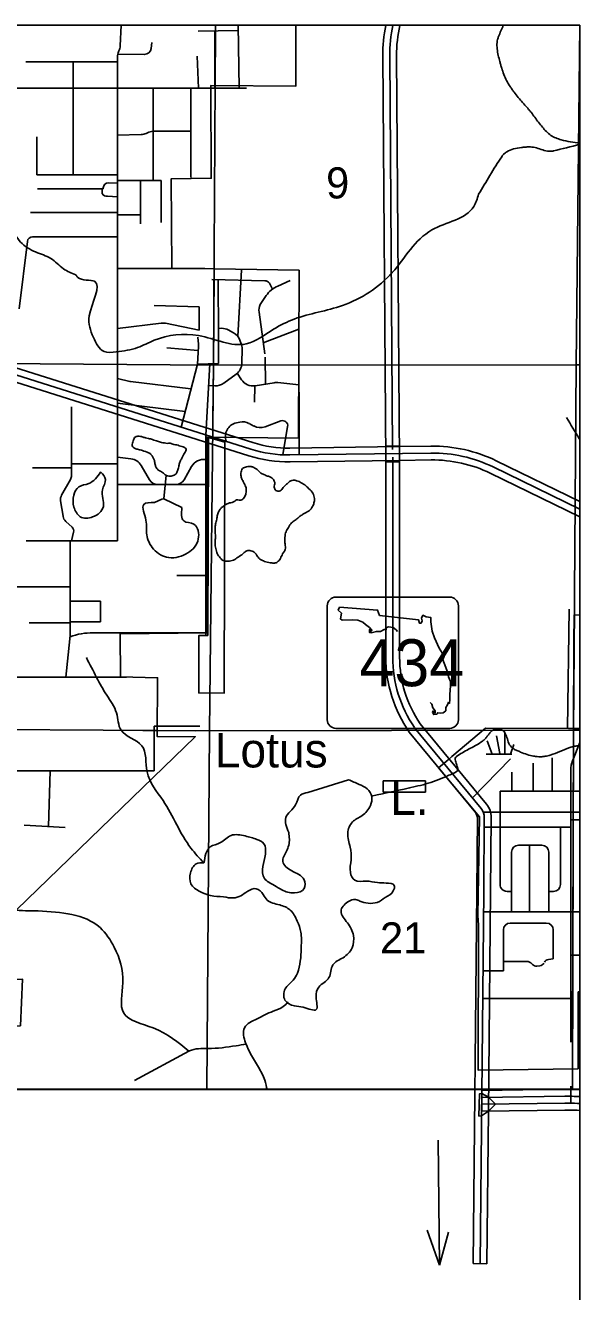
# Model space of a CAD drawing. Extents: x 2157516 to 2331756, y 2153820 to 2265756.
# Drawn here: x 2249249 to 2265958, y 2184545 to 2222724 of the extents above; entities that cross this region are included whole.
import ezdxf

# ---------------------------------------------------------------- set-up
doc = ezdxf.new("R2010")
doc.units = 0
doc.layers.add('Default', color=7, linetype='Continuous')
doc.layers.add('MapOutline_dp', color=7, linetype='Continuous')

msp = doc.modelspace()

# ---------------------------------------------------------------- linework, layer by layer
at = {"layer": 'Default'}
for p, q in [((2252133, 2222724), (2252107, 2222104)), ((2254463, 2222547), (2255663, 2222570)), ((2254980, 2222724), (2254920, 2212483)), ((2254958, 2220833), (2254958, 2222556)), ((2254980, 2222724), (2254969, 2220790)), ((2255697, 2220833), (2255660, 2222724)), ((2265958, 2222724), (2265856, 2212486)), ((2253065, 2222206), (2253043, 2222030)), ((2249263, 2221619), (2252030, 2221619)), ((2250686, 2220833), (2250686, 2221619)), ((2252030, 2221813), (2252030, 2220833)), ((2252836, 2221847), (2252033, 2221852)), ((2252072, 2221953), (2252047, 2221897)), ((2254468, 2220833), (2254429, 2221795)), ((2260023, 2221802), (2260113, 2209601)), ((2260232, 2221803), (2260320, 2209934)), ((2260440, 2221805), (2260530, 2209607)), ((2247650, 2220833), (2255920, 2220833)), ((2250686, 2218217), (2250686, 2220833)), ((2252030, 2211213), (2252030, 2220833)), ((2253099, 2218042), (2253099, 2220833)), ((2254238, 2218135), (2254238, 2220833)), ((2249596, 2219357), (2249596, 2218217)), ((2252030, 2219409), (2252740, 2219429)), ((2252890, 2219462), (2252975, 2219498)), ((2253137, 2219531), (2254238, 2219531)), ((2249596, 2218217), (2252030, 2218217)), ((2249613, 2217792), (2251597, 2217792)), ((2251565, 2217792), (2251564, 2217648)), ((2251597, 2217792), (2251599, 2217827)), ((2251758, 2217975), (2252030, 2217970)), ((2252030, 2218042), (2253340, 2218042)), ((2252720, 2216736), (2252720, 2218042)), ((2253340, 2218042), (2253340, 2216782)), ((2251730, 2217572), (2252030, 2217555)), ((2249405, 2217085), (2252030, 2217085)), ((2252030, 2217010), (2252720, 2217010)), ((2252030, 2216345), (2249466, 2216345)), ((2249311, 2216208), (2249064, 2214181)), ((2252030, 2215388), (2254655, 2215388)), ((2255659, 2213338), (2255761, 2215351)), ((2254866, 2215064), (2256473, 2215025)), ((2255066, 2215059), (2255071, 2213397)), ((2256605, 2214946), (2256703, 2214773)), ((2257229, 2215030), (2256857, 2214863)), ((2256511, 2214574), (2256327, 2214305)), ((2254484, 2214236), (2253128, 2214277)), ((2254484, 2213537), (2254484, 2214236)), ((2256294, 2214078), (2256466, 2212819)), ((2252030, 2213579), (2253339, 2213746)), ((2253475, 2213742), (2254484, 2213537)), ((2255071, 2213588), (2255166, 2213591)), ((2254446, 2213321), (2254468, 2213116)), ((2255071, 2213397), (2255074, 2212530)), ((2255366, 2213540), (2255526, 2213453)), ((2255715, 2213236), (2255758, 2213125)), ((2256420, 2213154), (2257491, 2213561)), ((2257491, 2213561), (2257500, 2209774)), ((2254461, 2212924), (2253519, 2212996)), ((2254469, 2213045), (2254434, 2212506)), ((2255785, 2212969), (2255776, 2212537)), ((2254920, 2212483), (2243791, 2212557)), ((2247922, 2212509), (2256048, 2209944)), ((2256048, 2209944), (2247922, 2212509)), ((2247984, 2212708), (2256111, 2210143)), ((2254434, 2212506), (2253944, 2210608)), ((2255074, 2212530), (2254434, 2212506)), ((2254692, 2210372), (2254808, 2212520)), ((2254920, 2212483), (2254804, 2201455)), ((2265856, 2212486), (2254920, 2212483)), ((2256474, 2212717), (2256484, 2211907)), ((2265856, 2212486), (2265772, 2201473)), ((2265958, 2212485), (2265856, 2212486)), ((2255985, 2209746), (2247859, 2212311)), ((2252030, 2212081), (2252403, 2211989)), ((2255604, 2212208), (2255229, 2211936)), ((2255635, 2212232), (2255765, 2212038)), ((2252415, 2211987), (2252403, 2211989)), ((2252415, 2211987), (2254242, 2211762)), ((2254958, 2211857), (2254773, 2211869)), ((2256164, 2211857), (2256156, 2211366)), ((2256176, 2211859), (2256750, 2211949)), ((2256750, 2211949), (2256750, 2211949)), ((2256856, 2211953), (2257495, 2211889)), ((2252030, 2211328), (2254066, 2211082)), ((2250640, 2209156), (2250640, 2211217)), ((2252030, 2211213), (2252030, 2207181)), ((2255612, 2210739), (2255711, 2210760)), ((2255991, 2210722), (2256139, 2210644)), ((2256476, 2210622), (2256948, 2210796)), ((2257156, 2210624), (2257013, 2209774)), ((2254692, 2204329), (2254692, 2210372)), ((2257223, 2209979), (2260527, 2210023)), ((2257226, 2209771), (2261475, 2209827)), ((2261475, 2209827), (2257226, 2209771)), ((2260527, 2210023), (2261473, 2210036)), ((2249463, 2209386), (2250640, 2209386)), ((2250640, 2209506), (2252030, 2209506)), ((2252030, 2209706), (2252433, 2209657)), ((2252742, 2209454), (2252996, 2209018)), ((2254260, 2209424), (2254032, 2209021)), ((2260528, 2209607), (2257229, 2209562)), ((2260113, 2209601), (2260113, 2203674)), ((2260322, 2209701), (2260322, 2203674)), ((2261478, 2209619), (2260528, 2209607)), ((2260530, 2209607), (2260530, 2203674)), ((2263353, 2209408), (2265958, 2208140)), ((2265958, 2208140), (2263353, 2209408)), ((2263444, 2209595), (2265958, 2208372)), ((2250343, 2208559), (2250607, 2209028)), ((2251526, 2209253), (2251518, 2209253)), ((2253419, 2208446), (2253496, 2209157)), ((2265958, 2207909), (2263262, 2209221)), ((2252030, 2208878), (2254692, 2208878)), ((2250386, 2207921), (2250312, 2208391)), ((2255398, 2208326), (2255401, 2208328)), ((2250656, 2207596), (2250467, 2207769)), ((2252030, 2207181), (2249272, 2207181)), ((2250599, 2204396), (2250599, 2207181)), ((2250640, 2207181), (2250702, 2207445)), ((2250640, 2207181), (2250640, 2207181)), ((2253814, 2206141), (2254692, 2206141)), ((2242378, 2205792), (2250599, 2205792)), ((2250599, 2205368), (2251514, 2205368)), ((2251514, 2205368), (2251514, 2204744)), ((2258348, 2205224), (2258348, 2201789)), ((2262043, 2205484), (2258608, 2205484)), ((2262303, 2201789), (2262303, 2205224)), ((2265640, 2205124), (2265589, 2201528)), ((2249367, 2204710), (2250599, 2204710)), ((2251514, 2204744), (2250599, 2204744)), ((2254747, 2204411), (2251296, 2204411)), ((2250473, 2203067), (2250590, 2204229)), ((2243735, 2203067), (2252299, 2203067)), ((2254804, 2201455), (2243775, 2201524)), ((2252794, 2201468), (2254392, 2201458)), ((2253136, 2200251), (2253136, 2201591)), ((2253136, 2201591), (2254510, 2201591)), ((2254804, 2201455), (2254715, 2190662)), ((2265772, 2201473), (2254804, 2201455)), ((2258608, 2201529), (2262043, 2201529)), ((2260822, 2201417), (2262829, 2198979)), ((2260982, 2201549), (2262990, 2199112)), ((2263150, 2199244), (2261154, 2201667)), ((2263701, 2201426), (2263701, 2200747)), ((2265620, 2201528), (2265958, 2201528)), ((2265772, 2201473), (2265740, 2190663)), ((2265958, 2201472), (2265772, 2201473)), ((2263173, 2201149), (2263324, 2200747)), ((2263450, 2201300), (2263550, 2200772)), ((2263975, 2201041), (2263877, 2200747)), ((2265958, 2201103), (2265747, 2200568)), ((2262725, 2199433), (2263872, 2200609)), ((2263137, 2200747), (2263913, 2200747)), ((2265128, 2199632), (2265128, 2200638)), ((2243735, 2200251), (2253136, 2200251)), ((2250000, 2200251), (2249951, 2198565)), ((2264554, 2199632), (2264554, 2200484)), ((2265689, 2200263), (2265689, 2193050)), ((2257764, 2199592), (2258988, 2199981)), ((2263913, 2199632), (2263913, 2200203)), ((2265958, 2199632), (2263560, 2199632)), ((2263560, 2199632), (2263560, 2196822)), ((2262829, 2198979), (2262876, 2198845)), ((2262876, 2198845), (2262858, 2196614)), ((2265958, 2198999), (2263056, 2198999)), ((2263084, 2198843), (2263066, 2196612)), ((2263274, 2196611), (2263293, 2198842)), ((2265689, 2198766), (2265958, 2198766)), ((2249218, 2198609), (2250448, 2198535)), ((2263082, 2198546), (2265689, 2198546)), ((2265382, 2196820), (2265382, 2198546)), ((2264820, 2198005), (2264113, 2198005)), ((2264450, 2195996), (2264450, 2198005)), ((2263905, 2197797), (2263905, 2195996)), ((2265028, 2195996), (2265028, 2197797)), ((2262858, 2196614), (2262746, 2185391)), ((2263066, 2196612), (2262954, 2185389)), ((2263208, 2189990), (2263274, 2196611)), ((2263768, 2196614), (2263905, 2196614)), ((2265028, 2196612), (2265173, 2196612)), ((2263060, 2195996), (2265958, 2195996)), ((2264953, 2195659), (2263868, 2195659)), ((2263660, 2195451), (2263660, 2194216)), ((2265161, 2194582), (2265161, 2195451)), ((2263668, 2194503), (2264360, 2194503)), ((2265016, 2194564), (2265161, 2194582)), ((2265689, 2194690), (2265958, 2194690)), ((2263660, 2194216), (2263042, 2194216)), ((2264519, 2194429), (2264534, 2194411)), ((2264671, 2194357), (2264760, 2194367)), ((2263034, 2193384), (2265689, 2193384)), ((2265909, 2193586), (2265958, 2193585)), ((2265689, 2193050), (2265691, 2192068)), ((2254182, 2191797), (2252538, 2190909)), ((2265692, 2190740), (2265693, 2190229)), ((2263000, 2189987), (2263004, 2190403)), ((2263001, 2190611), (2265504, 2190646)), ((2263004, 2190403), (2265507, 2190438)), ((2263163, 2185387), (2263208, 2189990)), ((2261729, 2185341), (2261696, 2189112)), ((2261729, 2185341), (2261366, 2186396)), ((2261729, 2185341), (2262004, 2186341)), ((2262746, 2185391), (2263163, 2185387)), ((2262746, 2185391), (2263163, 2185387))]:
    msp.add_line(p, q, dxfattribs=at)
for points in [[(2265958, 2190664), (2245319, 2190652), (2245307, 2191654), (2245319, 2192549), (2249099, 2192561), (2249167, 2193966), (2246762, 2193921), (2254372, 2201275), (2253227, 2201282), (2253233, 2203055), (2252119, 2203079), (2252103, 2204383), (2254726, 2204410), (2254718, 2210303), (2257483, 2210276), (2257499, 2215340), (2253665, 2215400), (2253649, 2218097), (2254852, 2218113), (2254836, 2220906), (2257403, 2220890), (2257403, 2222724)], [(2254936, 2215232), (2254920, 2212483), (2254903, 2210838)], [(2253968, 2208184), (2253419, 2208446), (2253366, 2208435), (2253145, 2208341)], [(2260470, 2204445), (2260429, 2204498), (2260340, 2204574), (2260196, 2204594), (2260134, 2204567), (2260127, 2204505), (2260066, 2204512), (2259956, 2204450), (2259832, 2204450), (2259674, 2204409), (2259619, 2204423), (2259626, 2204512), (2259661, 2204450), (2259695, 2204484), (2259619, 2204574), (2259503, 2204663), (2259427, 2204725), (2259276, 2204793), (2259118, 2204800), (2258796, 2204793), (2258748, 2204828), (2258775, 2205006), (2258679, 2205096), (2258714, 2205178)], [(2258714, 2205178), (2259866, 2205096), (2259928, 2204931), (2261102, 2204800), (2261129, 2204704), (2261177, 2204704), (2261212, 2204773), (2261191, 2204855), (2261232, 2204938), (2261335, 2204890), (2261472, 2204869), (2261472, 2204739), (2261514, 2204457), (2261582, 2204258), (2261726, 2203949), (2261822, 2203784), (2261877, 2203709), (2261836, 2203592), (2261891, 2203448), (2261960, 2203248), (2262008, 2203084), (2262063, 2202939), (2262063, 2202809), (2262049, 2202548), (2262042, 2202397), (2262035, 2202280), (2262008, 2202315), (2261973, 2202239), (2261925, 2202157), (2261925, 2202061), (2261843, 2201999), (2261754, 2201985), (2261678, 2201999), (2261651, 2201958), (2261562, 2201944), (2261520, 2202019), (2261541, 2202054), (2261568, 2202006), (2261603, 2201992), (2261603, 2202054), (2261527, 2202143), (2261500, 2202253), (2261453, 2202304)], [(2265958, 2204945), (2265793, 2204949), (2265787, 2204131), (2265772, 2201524), (2263123, 2201539), (2262108, 2200675), (2261990, 2200578), (2261698, 2200334), (2262937, 2198857), (2262889, 2195888), (2262913, 2195592), (2262900, 2191220), (2265908, 2191265), (2265909, 2193586)], [(2265800, 2205138), (2265772, 2201473), (2265744, 2192040)], [(2233007, 2190644), (2265958, 2190644)], [(2263004, 2190403), (2265507, 2190438), (2265608, 2190439), (2265707, 2190437), (2265807, 2190434), (2265907, 2190430), (2265958, 2190426)], [(2265958, 2190009), (2265884, 2190014), (2265791, 2190018), (2265697, 2190021), (2265606, 2190022), (2265512, 2190022), (2263000, 2189987)], [(2263002, 2190195), (2265510, 2190230), (2265607, 2190231), (2265702, 2190229), (2265799, 2190226), (2265896, 2190222), (2265958, 2190218)]]:
    msp.add_lwpolyline(points, dxfattribs=at)
for points in [[(2254773, 2210302), (2254746, 2204329), (2254480, 2204330), (2254477, 2202595), (2255246, 2202593), (2255260, 2210157)], [(2260116, 2210040), (2260523, 2210040), (2260523, 2209560), (2260116, 2209560)], [(2260039, 2199944), (2261308, 2199944), (2261308, 2199609), (2260039, 2199609)], [(2263005, 2190520), (2263213, 2190406), (2263419, 2190201), (2263208, 2189990), (2262999, 2189845), (2262919, 2189839), (2262943, 2190514)]]:
    msp.add_lwpolyline(points, close=True, dxfattribs=at)
for centre, radius, start, end in [((2264395, 2221834), 4372, 168.2633, 180.4261), ((2264395, 2221834), 4164, 167.6675, 180.4261), ((2264395, 2221834), 3956, 167.0073, 180.4261), ((2251691, 2222122), 416, 336.1246, 357.6139), ((2252837, 2222055), 208, 269.6876, 352.875), ((2252238, 2221813), 208, 156.1244, 179.9999), ((2252728, 2219846), 416, 271.6516, 292.9324), ((2253137, 2219115), 416, 90, 112.9325), ((2251755, 2217819), 156, 88.939, 177.3018), ((2251700, 2217725), 156, 209.3577, 281.3099), ((2249466, 2216189), 156, 90, 173.0636), ((2256469, 2214869), 156, 29.5387, 88.614), ((2257198, 2214104), 833, 114.2012, 145.5977), ((2256707, 2214134), 416, 155.8714, 187.7869), ((2253392, 2213333), 416, 78.5412, 97.3006), ((2255166, 2213175), 416, 61.3268, 90), ((2255326, 2213087), 416, 20.8533, 61.3271), ((2254054, 2213072), 416, 356.2276, 6.054), ((2255368, 2212977), 416, 358.8765, 20.8543), ((2255360, 2212545), 416, 305.9523, 358.8767), ((2254984, 2212273), 416, 266.4237, 305.9523), ((2256111, 2212270), 416, 213.8509, 279.0017), ((2256815, 2211538), 416, 84.3594, 99.0016), ((2255698, 2210332), 416, 101.9293, 201.8651), ((2255797, 2210353), 416, 62.354, 101.9291), ((2256332, 2211013), 416, 242.3538, 290.2727), ((2257002, 2210650), 156, 350.4889, 110.2726), ((2257176, 2213518), 3539, 252.4813, 270.7668), ((2257176, 2213518), 3747, 252.4813, 270.7668), ((2257176, 2213518), 3747, 252.4813, 270.7668), ((2261531, 2205664), 4372, 64.0482, 90.7668), ((2261531, 2205664), 4164, 64.0482, 90.7668), ((2261531, 2205664), 4164, 64.0482, 90.7668), ((2252382, 2209244), 416, 30.2879, 83.0463), ((2254622, 2209219), 416, 80.4042, 150.4948), ((2257176, 2213518), 3956, 252.4813, 270.7668), ((2261531, 2205664), 3956, 64.0482, 90.7668), ((2250380, 2209156), 260, 330.6039, 359.9999), ((2253239, 2209159), 281, 210.2878, 269.9999), ((2253787, 2209159), 281, 270, 330.4949), ((2250569, 2208431), 260, 150.6039, 188.9453), ((2250643, 2207961), 260, 188.9451, 227.3858), ((2250550, 2207481), 156, 346.7592, 47.3859), ((2258608, 2205224), 260, 90, 180), ((2262043, 2205224), 260, 0, 90), ((2251296, 2202329), 2082, 90, 109.6672), ((2248933, 2204396), 1665, 354.2237, 359.9998), ((2264097, 2203684), 3984, 180.1462, 214.6899), ((2264069, 2203674), 3747, 179.9998, 214.5435), ((2264069, 2203674), 3539, 179.9998, 214.5435), ((2258608, 2201789), 260, 180, 270), ((2262043, 2201789), 260, 270, 360), ((2266522, 2200263), 833, 158.5232, 179.9998), ((2262668, 2198847), 416, 359.5254, 39.4733), ((2262668, 2198847), 625, 359.5254, 39.4733), ((2264113, 2197797), 208, 90, 179.9999), ((2264820, 2197797), 208, 359.9998, 89.9998), ((2263768, 2196822), 208, 179.9998, 269.9998), ((2265173, 2196820), 208, 270, 359.9999), ((2263868, 2195451), 208, 90, 179.9999), ((2264953, 2195451), 208, 359.9998, 89.9998), ((2264360, 2194295), 208, 40.0302, 89.9999), ((2265035, 2194409), 156, 97.125, 153.4349), ((2264653, 2194512), 156, 220.03, 276.519), ((2264742, 2194522), 156, 276.5196, 333.4349), ((2265587, 2184711), 5935, 86.4153, 90.7961), ((2265587, 2184711), 5727, 86.2848, 90.7961)]:
    msp.add_arc(centre, radius, start, end, dxfattribs=at)
for points in [[(2265958, 2219173), (2265401, 2219271), (2265090, 2219407), (2264834, 2219653), (2264605, 2219951), (2264493, 2220101), (2264435, 2220173), (2264376, 2220242), (2264239, 2220395), (2264107, 2220550), (2263980, 2220709), (2263919, 2220793), (2263860, 2220879), (2263756, 2221057), (2263674, 2221242), (2263607, 2221433), (2263578, 2221530), (2263551, 2221629), (2263504, 2221818), (2263471, 2222013), (2263469, 2222205), (2263484, 2222297), (2263514, 2222387), (2263657, 2222724)], [(2265958, 2219137), (2265167, 2218938), (2265122, 2218929), (2265076, 2218926), (2264984, 2218933), (2264798, 2218981), (2264612, 2219038), (2264519, 2219055), (2264426, 2219059), (2264315, 2219051), (2264200, 2219040), (2263968, 2218997), (2263761, 2218911), (2263677, 2218846), (2263641, 2218807), (2263610, 2218763), (2262912, 2217631)], [(2262912, 2217631), (2262767, 2217259), (2261502, 2216554), (2260309, 2215271), (2258809, 2214277), (2257357, 2213869), (2256728, 2213560), (2255908, 2213119), (2254471, 2213369), (2253134, 2213227), (2252634, 2213010), (2251988, 2212877), (2251622, 2212890), (2251301, 2213315), (2251176, 2213964), (2251334, 2215006), (2250830, 2215126), (2250768, 2215197)], [(2250768, 2215197), (2250399, 2215384), (2250016, 2215696), (2249555, 2215891), (2249105, 2216191), (2248939, 2216400)], [(2265958, 2210241), (2265946, 2210261), (2265563, 2210903)], [(2252780, 2209901), (2252713, 2209923), (2252663, 2209937), (2252605, 2209950), (2252518, 2209985), (2252473, 2210045), (2252479, 2210128), (2252497, 2210194), (2252544, 2210293), (2252641, 2210337), (2252716, 2210332), (2252775, 2210318), (2252874, 2210287), (2252958, 2210269), (2253087, 2210233), (2253236, 2210185), (2253357, 2210149), (2253523, 2210121)], [(2253523, 2210121), (2253611, 2210124), (2253727, 2210088), (2253815, 2210074), (2253890, 2210048), (2254048, 2209995), (2254097, 2209944), (2254066, 2209853), (2254031, 2209791), (2253984, 2209713), (2253941, 2209626), (2253893, 2209523), (2253874, 2209419), (2253835, 2209294), (2253795, 2209203), (2253740, 2209163), (2253610, 2209132), (2253531, 2209141), (2253440, 2209193), (2253378, 2209248), (2253267, 2209309), (2253197, 2209389), (2253161, 2209482), (2253138, 2209603), (2253106, 2209683), (2253053, 2209767), (2253037, 2209784), (2253012, 2209814), (2252963, 2209840), (2252780, 2209901)], [(2257631, 2207991), (2257673, 2208016), (2257816, 2208096), (2257906, 2208216), (2257950, 2208323), (2257961, 2208456), (2257917, 2208616), (2257799, 2208751), (2257704, 2208840), (2257568, 2208935), (2257427, 2208995), (2257323, 2209010), (2257184, 2208942), (2257103, 2208868), (2257022, 2208786), (2256928, 2208688), (2256799, 2208703), (2256751, 2208799), (2256766, 2208937), (2256726, 2209029), (2256639, 2209106), (2256552, 2209136), (2256436, 2209180), (2256349, 2209224), (2256295, 2209275), (2256234, 2209334), (2256139, 2209390), (2256056, 2209421), (2255918, 2209415), (2255795, 2209359), (2255747, 2209222), (2255757, 2209101), (2255802, 2208996), (2255846, 2208908), (2255902, 2208777), (2255909, 2208698), (2255899, 2208611), (2255847, 2208486), (2255741, 2208413), (2255582, 2208400), (2255561, 2208379), (2255398, 2208326)], [(2251518, 2209253), (2251360, 2209049), (2251160, 2208907), (2250865, 2208812), (2250707, 2208554), (2250715, 2208200), (2250906, 2207909), (2251277, 2207901), (2251601, 2208217), (2251572, 2208720), (2251663, 2209036), (2251526, 2209253)], [(2253145, 2208341), (2252816, 2208279), (2252886, 2207805), (2252907, 2207364), (2253115, 2206932), (2253573, 2206678), (2254147, 2206819), (2254463, 2207235), (2254330, 2207680), (2254026, 2207780), (2253968, 2208184)], [(2255401, 2208328), (2255317, 2208288), (2255237, 2208239), (2255182, 2208198), (2255122, 2208133), (2255062, 2208030), (2255030, 2207897), (2255003, 2207764), (2254971, 2207623), (2254975, 2207402), (2254977, 2207252), (2254966, 2207135), (2254981, 2206993), (2255020, 2206834), (2255097, 2206699), (2255208, 2206593), (2255366, 2206569), (2255525, 2206604), (2255661, 2206689), (2255804, 2206791), (2255885, 2206860), (2255977, 2206892), (2256119, 2206856), (2256209, 2206775), (2256246, 2206712), (2256283, 2206661), (2256361, 2206605), (2256494, 2206553), (2256681, 2206516), (2256781, 2206514), (2256874, 2206567), (2256952, 2206686), (2257025, 2206818), (2257085, 2206917), (2257076, 2207088), (2257074, 2207239), (2257094, 2207426), (2257163, 2207550), (2257249, 2207694), (2257355, 2207788), (2257461, 2207869), (2257529, 2207926), (2257631, 2207991)], [(2251088, 2203663), (2251397, 2203064), (2251701, 2202530), (2251996, 2201997), (2252134, 2201472), (2252759, 2201006), (2252921, 2200214), (2253400, 2199352), (2254242, 2197915), (2254633, 2197474)], [(2259688, 2199486), (2260995, 2199772), (2261316, 2199852), (2261631, 2199954), (2261940, 2200077), (2262092, 2200148), (2262242, 2200224), (2262276, 2200261), (2262281, 2200314), (2262244, 2200449), (2262206, 2200585), (2262222, 2200662), (2262242, 2200679), (2262611, 2200898), (2263027, 2201144), (2263107, 2201209), (2263174, 2201292), (2263238, 2201377), (2263310, 2201452), (2263379, 2201490), (2263461, 2201509), (2263544, 2201509), (2263614, 2201489), (2263715, 2201378), (2263778, 2201209), (2263847, 2201035), (2263969, 2200910), (2264069, 2200860), (2264170, 2200815), (2264372, 2200739), (2264574, 2200690), (2264675, 2200677), (2264777, 2200673), (2264923, 2200687), (2265070, 2200723), (2265364, 2200834), (2265658, 2200948), (2265804, 2200989), (2265951, 2201010), (2265958, 2201011)], [(2258988, 2199981), (2259309, 2199840), (2259554, 2199702), (2259691, 2199473), (2259650, 2199203), (2259400, 2198899), (2259113, 2198708), (2258968, 2198371), (2259038, 2197947), (2259067, 2197564), (2259047, 2197186), (2259180, 2196949), (2259521, 2196924), (2259862, 2196878), (2260124, 2196865), (2260369, 2196795), (2260340, 2196628), (2260099, 2196429), (2259858, 2196283), (2259579, 2196258), (2259334, 2196321), (2259205, 2196370), (2258968, 2196296), (2258764, 2196017), (2258955, 2195667), (2259138, 2195281), (2259101, 2194915), (2258826, 2194615), (2258518, 2194395), (2258402, 2194016), (2258094, 2193729), (2258011, 2193430), (2258019, 2193051), (2257628, 2193118), (2257358, 2193163), (2257075, 2193338), (2257079, 2193671), (2257325, 2193937), (2257449, 2194149), (2257537, 2194507), (2257566, 2194935), (2257553, 2195385), (2257445, 2195717), (2257233, 2196050), (2256917, 2196204), (2256538, 2196350), (2256418, 2196520), (2256206, 2196695), (2255952, 2196620), (2255744, 2196479), (2255519, 2196416), (2255224, 2196445), (2254829, 2196487), (2254509, 2196612), (2254238, 2196845), (2254226, 2197169), (2254400, 2197444), (2254633, 2197474)], [(2257189, 2198388), (2257102, 2198838), (2257393, 2199227), (2257539, 2199519), (2257764, 2199592)], [(2254633, 2197474), (2254825, 2197955), (2255132, 2198084), (2255449, 2198300), (2255877, 2198284), (2256231, 2198180), (2256439, 2198051), (2256484, 2197731), (2256409, 2197365), (2256455, 2197003), (2256755, 2196795), (2256983, 2196657), (2257358, 2196570), (2257657, 2196703), (2257649, 2196961), (2257279, 2197236), (2257008, 2197510), (2257121, 2197822), (2257208, 2198192), (2257189, 2198388)], [(2247209, 2195935), (2247664, 2196049), (2248273, 2196028), (2248868, 2196049), (2249256, 2196028), (2249631, 2196028)], [(2249631, 2196028), (2251501, 2195520), (2251930, 2194929), (2252188, 2193858), (2252213, 2192942), (2253104, 2192496), (2254182, 2191797)], [(2255906, 2192010), (2255890, 2192049), (2255856, 2192502), (2256235, 2192772), (2256468, 2192889), (2256721, 2193001), (2257021, 2193138), (2257171, 2193279)], [(2254182, 2191797), (2254196, 2191804), (2254754, 2191875), (2255600, 2191959), (2255906, 2192010)], [(2256534, 2190626), (2256464, 2190921), (2256276, 2191312), (2256039, 2191716), (2255906, 2192010)]]:
    msp.add_spline(points, degree=3, dxfattribs=at)
at = {"layer": 'MapOutline_dp'}
msp.add_lwpolyline([(2224044, 2180484), (2265958, 2180484), (2265958, 2222724), (2224044, 2222724)], close=True, dxfattribs=at)

# ---------------------------------------------------------------- texts
at = {"layer": 'Default'}
for s, height, p in [('9', 937, (2258315, 2217505)), ('Lotus', 1040.9, (2254958, 2200350)), ('L.', 1040.9, (2260245, 2198921)), ('21', 936.8, (2259940, 2194743))]:
    msp.add_text(s, height=height, rotation=360, dxfattribs=at).set_placement(p)
msp.add_text('434', height=1415.7, dxfattribs=at).set_placement((2259319, 2202799))

doc.saveas('drawing.dxf')
